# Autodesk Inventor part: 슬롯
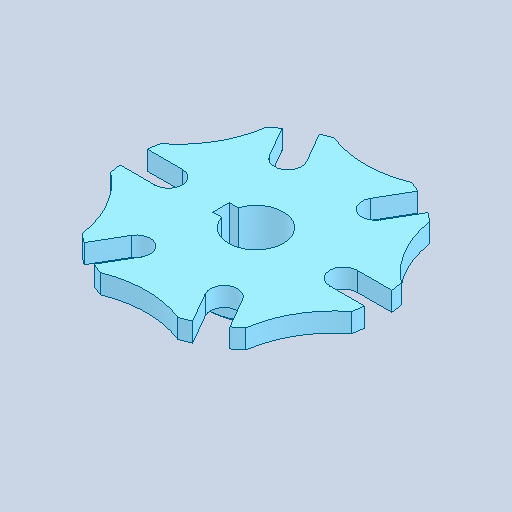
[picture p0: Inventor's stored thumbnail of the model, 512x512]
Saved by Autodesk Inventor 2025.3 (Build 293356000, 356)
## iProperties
Created: 2025-09
Part Number: 슬롯
Material: 강철, 합금
Document SubType Name: Modeling
Designer: PC-15
Density: 7.73 g/cm^3
Appearance: 기본값
Author: jhkim
Sending System: Autodesk Inventor 2026
Preprocessor: ST-DEVELOPER v20.1
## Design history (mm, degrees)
feature "솔리드1"
node "솔리드2"
